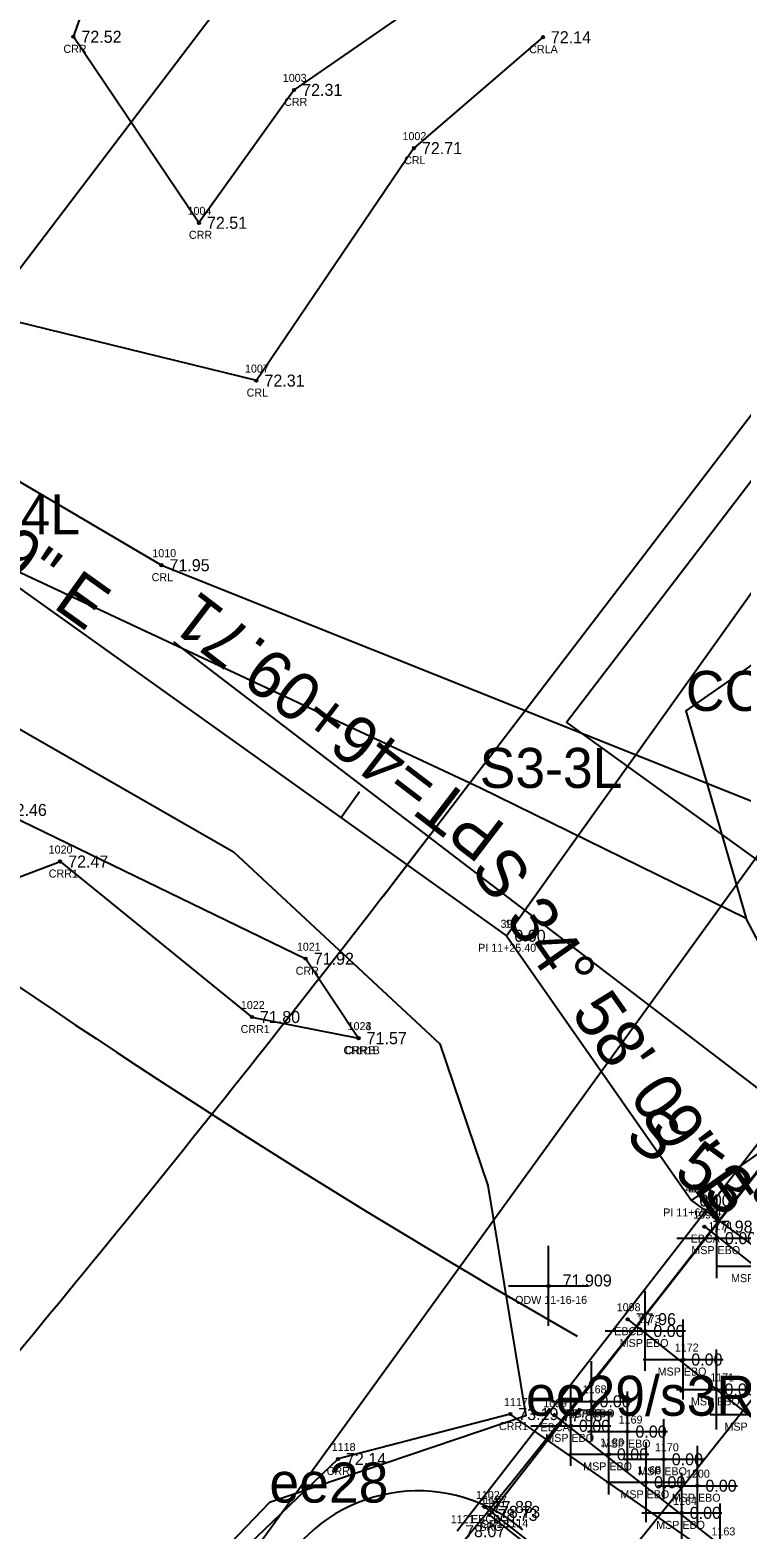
# Model space of a CAD drawing. Extents: x 2500794 to 2511032, y 910653 to 917533.
# Drawn here: x 2505698.2 to 2505787, y 913471.7 to 913659 of the extents above; entities that cross this region are included whole.
import ezdxf

# ---------------------------------------------------------------- set-up
doc = ezdxf.new("R2010")
doc.units = 0
for name, color, linetype in [('Default', 7, 'Continuous'), ('RD_EX_Bridge', 7, 'Continuous'), ('RD_EX_Bridge_txCode', 7, 'Continuous'), ('RD_EX_GuardRail', 7, 'Continuous'), ('RD_EX_GuardRail_txCode', 7, 'Continuous'), ('RD_EX_H2O', 7, 'Continuous'), ('RD_EX_H2O_txCode', 7, 'Continuous'), ('RD_EX_H2O_WetLd', 7, 'Continuous'), ('RD_EX_Misc', 7, 'Continuous'), ('RD_EX_Misc_txCode', 7, 'Continuous'), ('RD_EX_Road_txCode', 7, 'Continuous'), ('RD_EX_RW', 7, 'Continuous'), ('RD_EX_TX_Bridge_ELEV', 7, 'Continuous'), ('RD_EX_TX_GuardRail_ELEV', 7, 'Continuous'), ('RD_EX_TX_H2O_ELEV', 7, 'Continuous'), ('RD_EX_TX_Misc_ELEV', 7, 'Continuous'), ('RD_EX_TX_UT_ELEV', 7, 'Continuous'), ('RD_EX_UT', 7, 'Continuous'), ('RD_EX_UT_txCode', 7, 'Continuous'), ('RD_EX_VEG', 7, 'Continuous'), ('RD_EX_Wall', 7, 'Continuous'), ('RD_HC_Cl', 7, 'Continuous'), ('RD_HC_Data', 7, 'Continuous'), ('RD_HC_Data_Tic', 7, 'Continuous'), ('RD_HC_Survey_ELEV', 7, 'Continuous'), ('RD_HC_txCode', 7, 'Continuous'), ('RD_PD_BCA', 7, 'Continuous'), ('RD_PD_Bridge', 7, 'Continuous'), ('RD_SMD_Locator', 7, 'Continuous'), ('RD_XS_NPDES', 7, 'Continuous')]:
    doc.layers.add(name, color=color, linetype=linetype)

# ---------------------------------------------------------------- blocks, each defined once
blk = doc.blocks.new('POINT_DISPLAY')
at = {"layer": 'Default'}
blk.add_line((0, 0), (0, 0), dxfattribs=at)
blk = doc.blocks.new('Non-Wetland Waters (Tributaries)')
at = {"layer": 'Default'}
for points in [[(636472.197, 232037.165), (636470.066, 232041.194), (636461.608, 232045.336), (636444.397, 232053.387), (636441.101, 232054.059)], [(636437.461, 232049.468), (636446.058, 232047.739), (636453.797, 232043.307), (636460.346, 232037.221), (636461.867, 232032.723), (636463.078, 232025.417)]]:
    blk.add_lwpolyline(points, dxfattribs=at)
blk = doc.blocks.new('Wetlands')
at = {"layer": 'Default'}
for points in [[(636520.194, 232111.184), (636514.488, 232100.701), (636499.967, 232081.539), (636490.363, 232066.6), (636480.685, 232057.143), (636473.031, 232051.175), (636468.151, 232047.782), (636470.066, 232041.194), (636461.608, 232045.336), (636444.397, 232053.387), (636441.101, 232054.059), (636484.137, 232110.659), (636486.079, 232110.274), (636502.502, 232110.709), (636520.194, 232111.184)], [(636308.974, 231919.839), (636399.189, 232007.15), (636425.313, 232034.144), (636437.461, 232049.468), (636446.058, 232047.739), (636453.797, 232043.307), (636460.346, 232037.221), (636461.867, 232032.723), (636463.078, 232025.417), (636454.935, 232022.66), (636440.916, 232008.067), (636430.194, 231992.837)]]:
    blk.add_lwpolyline(points, dxfattribs=at)

msp = doc.modelspace()

# ---------------------------------------------------------------- linework, layer by layer
at = {"layer": 'RD_EX_Bridge'}
for p, q in [((2505782.44, 913509.52), (2505808.62, 913488.87)), ((2505799.18, 913477.1), (2505772.87, 913497.95)), ((2505763.68, 913485.96), (2505790.02, 913465.34)), ((2505781.2, 913454.13), (2505754.99, 913474.49))]:
    msp.add_line(p, q, dxfattribs=at)
msp.add_lwpolyline([(2505810.9, 913544.51), (2505835.38, 913525.37), (2505780.21, 913454.04), (2505755.58, 913473.5), (2505810.9, 913544.51)], dxfattribs=at)
at = {"layer": 'RD_EX_GuardRail'}
msp.add_line((2505810.69, 913543.93), (2505755.9, 913473.88), dxfattribs=at)
at = {"layer": 'RD_EX_H2O_txCode'}
for points in [[(2505757.9, 913670.02), (2505731.18, 913651.53), (2505719.28, 913634.92), (2505703.6, 913658.16), (2505725.09, 913718.19)], [(2505762.26, 913658.11), (2505746.15, 913644.25), (2505726.47, 913615.21), (2505674.21, 913628.01), (2505666.25, 913620.58), (2505714.6, 913592.15), (2505793.9, 913560.45), (2505801.32, 913552.8), (2505803.7, 913539.77), (2505832.63, 913516.96), (2505848.42, 913517.19), (2505881.86, 913528.44), (2505910.2, 913538.78), (2505939.3, 913544.45), (2505946.25, 913542.54), (2505974.65, 913535.18), (2506004.11, 913524.7), (2506052.03, 913515.47), (2506115.49, 913494.68), (2506138.05, 913548.89)], [(2505594.65, 913525.76), (2505599.08, 913569.22), (2505647.5, 913611.03), (2505694.26, 913561.57), (2505732.63, 913542.98), (2505739.24, 913533.06)], [(2505594.65, 913525.76), (2505643.36, 913532.93), (2505701.94, 913555.13), (2505725.91, 913535.7), (2505739.24, 913533.06)], [(2505789.47, 913464.31), (2505758.18, 913486.1), (2505736.66, 913480.49), (2505719.32, 913463.86), (2505699.9, 913439.21), (2505669.03, 913402.75), (2505628.5, 913357.9), (2505593, 913316.39), (2505556.58, 913279.8), (2505487.72, 913211.38), (2505413.81, 913149.81), (2505341.31, 913072.1)]]:
    msp.add_lwpolyline(points, dxfattribs=at)
at = {"layer": 'RD_EX_Misc'}
for p, q in [((2505784.01, 913503.08), (2505784.01, 913513.08)), ((2505762.96, 913497.11), (2505762.96, 913507.11)), ((2505779.01, 913508.08), (2505789.01, 913508.08)), ((2505783.96, 913504.58), (2505793.96, 913504.58)), ((2505757.96, 913502.11), (2505767.96, 913502.11)), ((2505775.06, 913491.48), (2505775.06, 913501.48)), ((2505779.8, 913487.91), (2505779.8, 913497.91)), ((2505770.06, 913496.48), (2505780.06, 913496.48)), ((2505783.95, 913484.18), (2505783.95, 913494.18)), ((2505768.33, 913482.69), (2505768.33, 913492.69)), ((2505774.8, 913492.91), (2505784.8, 913492.91)), ((2505765.76, 913479.63), (2505765.76, 913489.63)), ((2505772.82, 913478.91), (2505772.82, 913488.91)), ((2505778.95, 913489.18), (2505788.95, 913489.18)), ((2505763.33, 913487.69), (2505773.33, 913487.69)), ((2505760.76, 913484.63), (2505770.76, 913484.63)), ((2505770.5, 913476.07), (2505770.5, 913486.07)), ((2505777.36, 913475.45), (2505777.36, 913485.45)), ((2505783.15, 913486.03), (2505793.15, 913486.03)), ((2505767.82, 913483.91), (2505777.82, 913483.91)), ((2505775.15, 913472.58), (2505775.15, 913482.58)), ((2505775.15, 913472.58), (2505775.15, 913482.58)), ((2505765.5, 913481.07), (2505775.5, 913481.07)), ((2505781.57, 913472.15), (2505781.57, 913482.15)), ((2505772.36, 913480.45), (2505782.36, 913480.45)), ((2505770.15, 913477.58), (2505780.15, 913477.58)), ((2505770.15, 913477.58), (2505780.15, 913477.58)), ((2505776.57, 913477.15), (2505786.57, 913477.15)), ((2505779.61, 913468.76), (2505779.61, 913478.76)), ((2505774.61, 913473.76), (2505784.61, 913473.76)), ((2505784.41, 913464.94), (2505784.41, 913474.94))]:
    msp.add_line(p, q, dxfattribs=at)
at = {"layer": 'RD_EX_RW'}
for p, q in [((2505742.31, 913550.82), (2505814.97, 913645.86)), ((2505747.99, 913558.24), (2505777.74, 913597.15))]:
    msp.add_line(p, q, dxfattribs=at)
msp.add_arc((2504100.66, 914817.69), 2073.62, 319.67523, 322.60071, dxfattribs=at)
at = {"layer": 'RD_EX_UT'}
msp.add_line((2505812.64, 913550.18), (2505751.54, 913471.47), dxfattribs=at)
at = {"layer": 'RD_EX_VEG'}
msp.add_lwpolyline([(2506002.64, 913815.25), (2505883.7, 913669.64), (2505827.83, 913593.29), (2505814.43, 913589.15), (2505792.49, 913560.55), (2505725.64, 913468.24), (2505664.37, 913399.09), (2505478.33, 913221), (2505411.99, 913152.19), (2505339.13, 913074.53)], dxfattribs=at)
at = {"layer": 'RD_EX_Wall'}
msp.add_arc((2506299.01, 914423.83), 1069.92, 219.1169, 240.15367, dxfattribs=at)
at = {"layer": 'RD_HC_Cl'}
for p, q in [((2505655.63, 913618.69), (2505757.7, 913545.85)), ((2505757.7, 913545.85), (2505780.82, 913512.79)), ((2505780.82, 913512.79), (2505811.03, 913490.61))]:
    msp.add_line(p, q, dxfattribs=at)
msp.add_arc((2504100.66, 914817.69), 2148.62, 314.20692, 322.60071, dxfattribs=at)
at = {"layer": 'RD_HC_Data'}
for p, q in [((2505757.7, 913545.85), (2505825.06, 913640.23)), ((2505807.57, 913512.69), (2505716.15, 913582.58)), ((2505780.82, 913512.79), (2505875.8, 913579.22))]:
    msp.add_line(p, q, dxfattribs=at)
at = {"layer": 'RD_HC_Data_Tic'}
msp.add_line((2505737.03, 913560.6), (2505739.35, 913563.86), dxfattribs=at)
at = {"layer": 'RD_PD_BCA'}
for p, q in [((2505765.19, 913572.52), (2505977.56, 913850.28)), ((2505822.03, 913531.5), (2505765.19, 913572.52))]:
    msp.add_line(p, q, dxfattribs=at)
at = {"layer": 'RD_PD_Bridge'}
for radius, start in [(2131.62, 320.53548), (2165.62, 320.00634), (2165.62, 320.53548)]:
    msp.add_arc((2504100.66, 914817.69), radius, start, 322.60071, dxfattribs=at)
at = {"layer": 'RD_SMD_Locator'}
for centre in [(2505703.6, 913658.16), (2505762.26, 913658.11), (2505731.18, 913651.53), (2505746.15, 913644.25), (2505719.28, 913634.92), (2505726.47, 913615.21), (2505714.6, 913592.15), (2505701.94, 913555.13), (2505732.63, 913542.98), (2505725.91, 913535.7), (2505739.24, 913533.06), (2505739.24, 913533.06), (2505782.44, 913509.52), (2505784.01, 913508.08), (2505762.96, 913502.11), (2505772.87, 913497.95), (2505775.06, 913496.48), (2505779.8, 913492.91), (2505783.95, 913489.18), (2505768.33, 913487.69), (2505758.18, 913486.1), (2505763.68, 913485.96), (2505765.76, 913484.63), (2505772.82, 913483.91), (2505770.5, 913481.07), (2505736.66, 913480.49), (2505777.36, 913480.45), (2505775.15, 913477.58), (2505775.15, 913477.58), (2505781.57, 913477.15), (2505754.99, 913474.49), (2505755.58, 913473.5), (2505755.9, 913473.88), (2505779.61, 913473.76)]:
    msp.add_circle(centre, 0.15, dxfattribs=at)
at = {"layer": 'RD_XS_NPDES'}
msp.add_arc((2505746.67, 913456.5), 20, 49.1447, 145.1503, dxfattribs=at)

# ---------------------------------------------------------------- block references
at = {"layer": 'Default', "xscale": 3.937007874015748, "yscale": 3.937007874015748}
for name, p in [('Wetlands', (0, 0)), ('Non-Wetland Waters (Tributaries)', (0, 0)), ('POINT_DISPLAY', (2505780.12, 913573.94)), ('POINT_DISPLAY', (2505780.12, 913573.94)), ('POINT_DISPLAY', (2505754.36, 913564.32)), ('POINT_DISPLAY', (2505754.36, 913564.32)), ('POINT_DISPLAY', (2505760.15, 913485.89)), ('POINT_DISPLAY', (2505760.15, 913485.89)), ('POINT_DISPLAY', (2505728.09, 913475.04)), ('POINT_DISPLAY', (2505728.09, 913475.04))]:
    msp.add_blockref(name, p, dxfattribs=at)
at = {"layer": 'RD_EX_H2O', "xscale": 3.937007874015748, "yscale": 3.937007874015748}
msp.add_blockref('Non-Wetland Waters (Tributaries)', (0, 0), dxfattribs=at)
at = {"layer": 'RD_EX_H2O_WetLd', "xscale": 3.937007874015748, "yscale": 3.937007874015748}
msp.add_blockref('Wetlands', (0, 0), dxfattribs=at)

# ---------------------------------------------------------------- texts
at = {"layer": 'Default'}
for s, p in [('S3-4L', (2505686.6, 913596.01)), ('S3-4L', (2505686.6, 913596.01)), ('CC7', (2505780.12, 913573.94)), ('CC7', (2505780.12, 913573.94)), ('S3-3L', (2505754.36, 913564.32)), ('S3-3L', (2505754.36, 913564.32)), ('ee29/s3R bRIDGE', (2505760.15, 913485.89)), ('ee29/s3R bRIDGE', (2505760.15, 913485.89)), ('ee28', (2505728.09, 913475.04)), ('ee28', (2505728.09, 913475.04))]:
    msp.add_text(s, height=5, dxfattribs=at).set_placement(p)
at = {"layer": 'RD_EX_Bridge_txCode'}
for s, p in [('1095', (2505781.05, 913510.52)), ('EBCA', (2505780.72, 913507.52)), ('1098', (2505771.49, 913498.95)), ('EBCB', (2505771.17, 913495.95)), ('1099', (2505762.3, 913486.96)), ('EBCA', (2505761.97, 913483.96)), ('1102', (2505753.89, 913475.49)), ('1105', (2505754.48, 913474.5)), ('EBCB', (2505753.29, 913472.49)), ('BRC', (2505754.33, 913471.5))]:
    msp.add_text(s, height=1, dxfattribs=at).set_placement(p)
at = {"layer": 'RD_EX_GuardRail_txCode'}
for s, p in [('1107', (2505754.8, 913474.88)), ('GR1B', (2505754.48, 913471.88))]:
    msp.add_text(s, height=1, dxfattribs=at).set_placement(p)
at = {"layer": 'RD_EX_H2O_txCode'}
for s, p in [('CRR', (2505702.35, 913656.16)), ('CRLA', (2505760.55, 913656.11)), ('1003', (2505729.76, 913652.53)), ('CRR', (2505729.93, 913649.53)), ('1002', (2505744.72, 913645.25)), ('CRL', (2505744.92, 913642.25)), ('1004', (2505717.86, 913635.92)), ('CRR', (2505718.03, 913632.92)), ('1007', (2505725.04, 913616.21)), ('CRL', (2505725.24, 913613.21)), ('1010', (2505713.46, 913593.15)), ('CRL', (2505713.37, 913590.15)), ('1020', (2505700.51, 913556.13)), ('CRR1', (2505700.52, 913553.13)), ('1021', (2505731.52, 913543.98)), ('CRR', (2505731.37, 913540.98)), ('1022', (2505724.52, 913536.7)), ('1023', (2505737.86, 913534.06)), ('1024', (2505737.86, 913534.06)), ('CRR1', (2505724.49, 913533.7)), ('CRR1B', (2505737.35, 913531.06)), ('CRRB', (2505737.52, 913531.06)), ('1117', (2505757.4, 913487.1)), ('CRR1', (2505756.77, 913484.1)), ('1118', (2505735.88, 913481.49)), ('CRR1', (2505735.24, 913478.49))]:
    msp.add_text(s, height=1, dxfattribs=at).set_placement(p)
at = {"layer": 'RD_EX_Misc_txCode'}
for s, p in [('1174', (2505782.95, 913509.08)), ('MSP EBO', (2505780.81, 913506.08)), ('MSP EBO', (2505785.77, 913502.58)), ('ODW 11-16-16 ', (2505758.79, 913499.86)), ('1173', (2505774, 913497.48)), ('MSP EBO', (2505771.86, 913494.48)), ('1172', (2505778.74, 913493.91)), ('MSP EBO', (2505776.6, 913490.91)), ('1171', (2505783.17, 913490.18)), ('1168', (2505767.24, 913488.69)), ('MSP EBO', (2505780.76, 913487.18)), ('1167', (2505764.67, 913485.63)), ('MSP EBO', (2505765.13, 913485.69)), ('1169', (2505771.73, 913484.91)), ('MSP EBO', (2505784.95, 913484.03)), ('MSP EBO', (2505762.56, 913482.63)), ('1186', (2505769.41, 913482.07)), ('MSP EBO', (2505769.62, 913481.91)), ('1170', (2505776.26, 913481.45)), ('MSP EBO', (2505767.3, 913479.07)), ('1166', (2505774.04, 913478.58)), ('1165', (2505774.06, 913478.58)), ('MSP EBO', (2505774.16, 913478.45)), ('1200', (2505780.14, 913478.15)), ('MSP EBO', (2505771.95, 913475.58)), ('MSP EBO', (2505771.95, 913475.58)), ('MSP EBO', (2505778.37, 913475.15)), ('1164', (2505778.53, 913474.76)), ('MSP EBO', (2505776.42, 913471.76)), ('1163', (2505783.33, 913470.94))]:
    msp.add_text(s, height=1, dxfattribs=at).set_placement(p)
at = {"layer": 'RD_EX_Road_txCode'}
msp.add_text('1114', height=1, dxfattribs=at).set_placement((2505757.45, 913471.96))
at = {"layer": 'RD_EX_TX_Bridge_ELEV'}
for s, p in [('77.98', (2505783.44, 913508.77)), ('77.96', (2505773.87, 913497.2)), ('77.88', (2505764.68, 913485.21)), ('77.88', (2505755.99, 913473.74)), ('78.73', (2505756.58, 913472.75))]:
    msp.add_text(s, height=1.5, dxfattribs=at).set_placement(p)
at = {"layer": 'RD_EX_TX_GuardRail_ELEV'}
msp.add_text('78.73', height=1.5, dxfattribs=at).set_placement((2505756.9, 913473.13))
at = {"layer": 'RD_EX_TX_H2O_ELEV'}
for s, p in [('72.52', (2505704.6, 913657.41)), ('72.14', (2505763.26, 913657.36)), ('72.31', (2505732.18, 913650.78)), ('72.71', (2505747.15, 913643.5)), ('72.51', (2505720.28, 913634.17)), ('72.31', (2505727.47, 913614.46)), ('71.95', (2505715.6, 913591.4)), ('72.46', (2505695.26, 913560.82)), ('72.47', (2505702.94, 913554.38)), ('71.92', (2505733.63, 913542.23)), ('71.80', (2505726.91, 913534.95)), ('71.57', (2505740.24, 913532.31)), ('71.57', (2505740.24, 913532.31)), ('73.19', (2505759.18, 913485.35)), ('72.14', (2505737.66, 913479.74))]:
    msp.add_text(s, height=1.5, dxfattribs=at).set_placement(p)
at = {"layer": 'RD_EX_TX_Misc_ELEV'}
for s, p in [('0.00', (2505785.01, 913507.33)), ('71.909', (2505764.73, 913502.04)), ('0.00', (2505776.06, 913495.73)), ('0.00', (2505780.8, 913492.16)), ('0.00', (2505769.33, 913486.94)), ('0.00', (2505784.95, 913488.43)), ('0.00', (2505766.76, 913483.88)), ('0.00', (2505773.82, 913483.16)), ('0.00', (2505771.5, 913480.32)), ('0.00', (2505778.36, 913479.7)), ('0.00', (2505776.15, 913476.83)), ('0.00', (2505776.15, 913476.83)), ('0.00', (2505782.57, 913476.4)), ('0.00', (2505780.61, 913473.01))]:
    msp.add_text(s, height=1.5, dxfattribs=at).set_placement(p)
at = {"layer": 'RD_EX_TX_UT_ELEV'}
msp.add_text('78.07', height=1.5, dxfattribs=at).set_placement((2505752.54, 913470.72))
at = {"layer": 'RD_EX_UT_txCode'}
msp.add_text('1121', height=1, dxfattribs=at).set_placement((2505750.76, 913472.47))
at = {"layer": 'RD_HC_Data'}
for s, rotation, p in [('S 54%%d 29\' 09" E', 324.4859, (2505661.32, 913615.19)), ('PT=46+09.71', 142.6007, (2505757.86, 913559.5)), ('S 34%%d 58\' 09" E', 304.9692, (2505753.09, 913554.18)), ('S 53%%d 42\' 36" E', 323.7099, (2505772.28, 913520.3))]:
    msp.add_text(s, height=6, rotation=rotation, dxfattribs=at).set_placement(p)
at = {"layer": 'RD_HC_Survey_ELEV'}
for p in [(2505758.7, 913545.1), (2505758.7, 913545.1), (2505781.82, 913512.04), (2505781.82, 913512.04)]:
    msp.add_text('0.00', height=1.5, dxfattribs=at).set_placement(p)
at = {"layer": 'RD_HC_txCode'}
for s, p in [('39', (2505756.97, 913546.85)), ('11', (2505757.54, 913546.85)), ('PI 11+25.40', (2505754.17, 913543.85)), ('PI 11+25.40', (2505754.17, 913543.85)), ('40', (2505780.05, 913513.79)), ('12', (2505780.37, 913513.79)), ('PI 11+65.74', (2505777.3, 913510.79)), ('PI 11+65.74', (2505777.3, 913510.79))]:
    msp.add_text(s, height=1, dxfattribs=at).set_placement(p)

doc.saveas('drawing.dxf')
